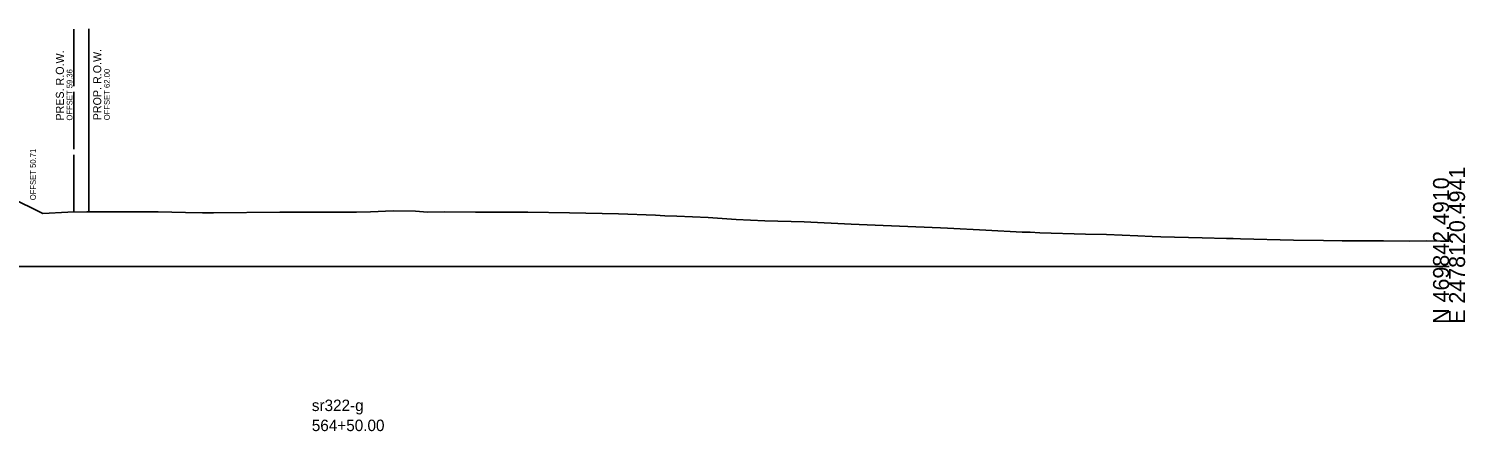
# Model space of a CAD drawing. Extents: x -26 to 4781, y -31 to 24738.
# Drawn here: x 2351.5 to 2602.8, y 14971.2 to 15041.6 of the extents above; entities that cross this region are included whole.
import ezdxf

# ---------------------------------------------------------------- set-up
doc = ezdxf.new("R2010")
doc.units = 0
for name, color, linetype in [('DESIGN - ROW - Right-of-Way and Easement Labels', 7, 'Continuous'), ('DESIGN - ROW - Right-of-Way Linework', 7, 'Continuous'), ('DESIGN - SHEET - Light Grid', 7, 'Continuous'), ('DESIGN - TYPICAL - Slope Tie Text', 7, 'Continuous'), ('DESIGN - TYPICAL - Warning Text', 7, 'Continuous'), ('SURVEY - GROUND - Top of Ground', 7, 'Continuous'), ('SURVEY - PROPERTY - ROW Lines', 7, 'Continuous'), ('SURVEY - PROPERTY - ROW Lines Text', 7, 'Continuous')]:
    doc.layers.add(name, color=color, linetype=linetype)

msp = doc.modelspace()

# ---------------------------------------------------------------- linework, layer by layer
at = {"layer": 'DESIGN - ROW - Right-of-Way Linework'}
msp.add_line((2362, 15009.59), (2362, 15041.59), dxfattribs=at)
at = {"layer": 'DESIGN - SHEET - Light Grid'}
msp.add_line((2300, 15000), (2600, 15000), dxfattribs=at)
at = {"layer": 'SURVEY - GROUND - Top of Ground'}
msp.add_lwpolyline([(2348.16, 15012.12), (2353.92, 15009.27), (2358.31, 15009.52), (2361.62, 15009.59), (2366.92, 15009.58), (2371.05, 15009.57), (2374.11, 15009.56), (2378.88, 15009.46), (2381.87, 15009.41), (2383.79, 15009.4), (2395.42, 15009.51), (2408.84, 15009.52), (2411.26, 15009.59), (2415.21, 15009.73), (2419.12, 15009.68), (2421.27, 15009.55), (2424.17, 15009.57), (2429.64, 15009.53), (2431.66, 15009.52), (2433.29, 15009.52), (2438.81, 15009.55), (2446.1, 15009.4), (2454.65, 15009.23), (2461.15, 15008.98), (2462.75, 15008.9), (2464.9, 15008.8), (2470.35, 15008.59), (2475.24, 15008.26), (2480.29, 15008.01), (2487.15, 15007.81), (2495.4, 15007.42), (2499.55, 15007.23), (2509.53, 15006.82), (2511.01, 15006.77), (2512.25, 15006.71), (2518.93, 15006.4), (2525.3, 15006.04), (2526.7, 15006), (2528.4, 15005.93), (2536.37, 15005.7), (2540.05, 15005.6), (2545.53, 15005.37), (2548.03, 15005.26), (2549.58, 15005.2), (2556.78, 15005.04), (2561.06, 15004.94), (2562.23, 15004.92), (2563.53, 15004.88), (2572.77, 15004.64), (2578.02, 15004.58), (2581.31, 15004.54), (2584.41, 15004.53), (2588.54, 15004.51), (2593.16, 15004.46), (2596.04, 15004.49), (2598.52, 15004.47), (2600, 15004.44)], dxfattribs=at)
at = {"layer": 'SURVEY - PROPERTY - ROW Lines'}
for p, q in [((2359.36, 15031.54), (2359.36, 15041.54)), ((2359.36, 15020.54), (2359.36, 15030.54)), ((2359.36, 15009.54), (2359.36, 15019.54))]:
    msp.add_line(p, q, dxfattribs=at)

# ---------------------------------------------------------------- texts
at = {"layer": 'DESIGN - ROW - Right-of-Way and Easement Labels'}
for s, height, p in [('PROP. R.O.W.', 1.4, (2364.15, 15025.59)), ('OFFSET 62.00', 1, (2365.65, 15025.59))]:
    msp.add_text(s, height=height, rotation=90, dxfattribs=at).set_placement(p)
at = {"layer": 'DESIGN - SHEET - Light Grid'}
for s, p in [('E 2478120.4941', (2602.8, 14990)), ('N 469842.4910', (2600, 14990))]:
    msp.add_text(s, height=2.8, rotation=90, dxfattribs=at).set_placement(p)
at = {"layer": 'DESIGN - TYPICAL - Slope Tie Text'}
msp.add_text('OFFSET 50.71', height=1, rotation=90, dxfattribs=at).set_placement((2352.71, 15011.61))
at = {"layer": 'DESIGN - TYPICAL - Warning Text'}
for s, p in [('sr322-g', (2401, 14974.75)), ('564+50.00', (2401, 14971.25))]:
    msp.add_text(s, height=2, dxfattribs=at).set_placement(p)
at = {"layer": 'SURVEY - PROPERTY - ROW Lines Text'}
for s, height, p in [('PRES. R.O.W.', 1.4, (2357.61, 15025.54)), ('OFFSET 59.36', 1, (2359.11, 15025.54))]:
    msp.add_text(s, height=height, rotation=90, dxfattribs=at).set_placement(p)

doc.saveas('drawing.dxf')
